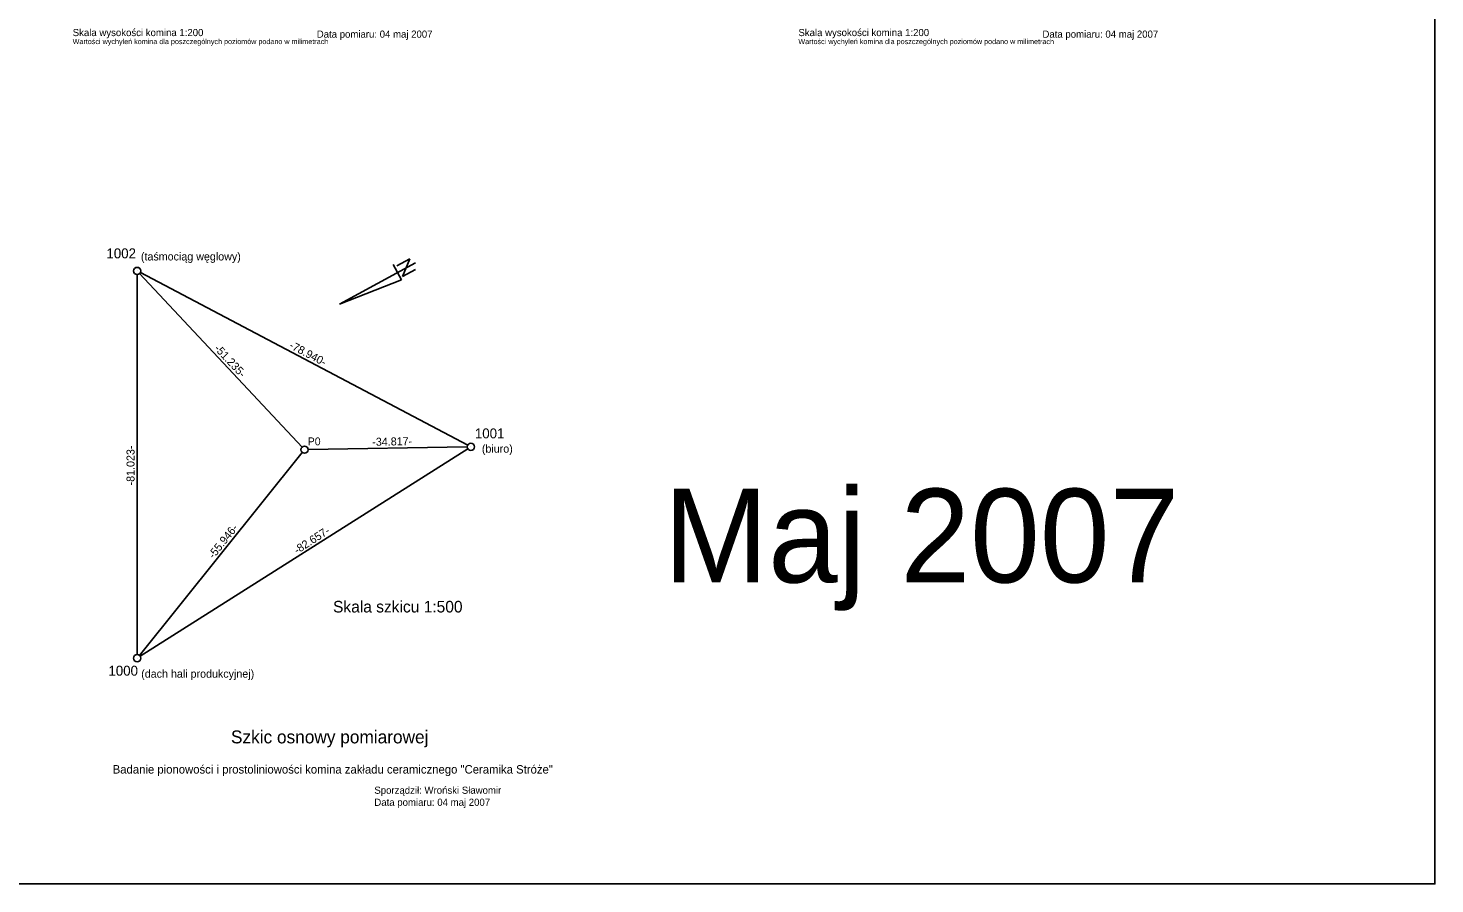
# Model space of a CAD drawing. Extents: x 138 to 264, y -75 to 121.
# Drawn here: x 196.8 to 257.1, y 47.8 to 84.5 of the extents above; entities that cross this region are included whole.
import ezdxf

# ---------------------------------------------------------------- set-up
doc = ezdxf.new("R2010")
doc.units = 0
for name, color, linetype in [('15 listopad 2008', 7, 'Continuous'), ('Default', 7, 'Continuous'), ('Opisy', 7, 'Continuous'), ('Standard', 7, 'Continuous')]:
    doc.layers.add(name, color=color, linetype=linetype)

msp = doc.modelspace()

# ---------------------------------------------------------------- linework, layer by layer
at = {"layer": '15 listopad 2008'}
msp.add_lwpolyline([(139.203, 110.337), (257.14, 110.337), (257.14, 47.785), (139.203, 47.785)], close=True, dxfattribs=at)
at = {"layer": 'Standard'}
for p, q in [((213.429, 74.415), (210.173, 72.634)), ((212.829, 73.679), (212.481, 74.337)), ((213.19, 74.583), (212.633, 74.286)), ((212.88, 73.823), (213.19, 74.583)), ((201.503, 74.063), (201.503, 74.063)), ((201.503, 73.909), (201.503, 69.047)), ((201.608, 73.951), (208.573, 66.513)), ((201.639, 73.991), (215.675, 66.593)), ((210.173, 72.634), (212.829, 73.679)), ((213.437, 74.12), (212.88, 73.823)), ((201.503, 69.047), (201.503, 67.567)), ((201.503, 67.567), (201.503, 57.616)), ((215.681, 66.439), (201.632, 57.544)), ((208.832, 66.403), (215.657, 66.519)), ((215.811, 66.522), (215.811, 66.522)), ((208.582, 66.281), (201.599, 57.582)), ((201.503, 57.462), (201.503, 57.462))]:
    msp.add_line(p, q, dxfattribs=at)
for centre in [(201.503, 74.063), (208.679, 66.401), (215.811, 66.522), (201.503, 57.462)]:
    msp.add_circle(centre, 0.154, dxfattribs=at)

# ---------------------------------------------------------------- texts
at = {"layer": 'Default'}
msp.add_text('Maj 2007', height=4.0171, dxfattribs=at).set_placement((224.08, 60.708))
at = {"layer": 'Opisy'}
for s, height, p in [('Skala wysokości komina 1:200', 0.30766, (198.739, 84.132)), ('Skala wysokości komina 1:200', 0.30766, (229.853, 84.132)), ('Wartości wychyleń komina dla poszczególnych poziomów podano w milimetrach', 0.22315, (198.736, 83.789)), ('Data pomiaru: 04 maj 2007', 0.30766, (209.202, 84.064)), ('Wartości wychyleń komina dla poszczególnych poziomów podano w milimetrach', 0.22315, (229.85, 83.789)), ('Data pomiaru: 04 maj 2007', 0.30766, (240.316, 84.064))]:
    msp.add_text(s, height=height, dxfattribs=at).set_placement(p)
at = {"layer": 'Standard'}
for s, height, p in [('1002', 0.426, (200.184, 74.604)), ('(taśmociąg węglowy)', 0.34308, (201.663, 74.513)), ('1001', 0.426, (215.981, 66.886)), ('P0', 0.3382, (208.814, 66.588)), ('(biuro)', 0.3431, (216.281, 66.273)), ('Skala szkicu 1:500', 0.49797, (209.9, 59.421)), ('1000', 0.426, (200.27, 56.711)), ('(dach hali produkcyjnej)', 0.34308, (201.675, 56.624)), ('Szkic osnowy pomiarowej', 0.55314, (205.523, 53.809)), ('Badanie pionowości i prostoliniowości komina zakładu ceramicznego "Ceramika Stróże"', 0.36281, (200.453, 52.514)), ('Sporządził: Wroński Sławomir', 0.30766, (211.671, 51.647)), ('Data pomiaru: 04 maj 2007', 0.30766, (211.671, 51.13))]:
    msp.add_text(s, height=height, dxfattribs=at).set_placement(p)
for s, rotation, p in [('-51.235-', 313.18745, (204.781, 70.716)), ('-78.940-', 332.12805, (207.99, 70.772)), ('-81.023-', 90, (201.389, 64.869)), ('-34.817-', 1.09229, (211.586, 66.565)), ('-55.946-', 51.39237, (204.78, 61.702)), ('-82.657-', 32.82854, (208.359, 61.913))]:
    msp.add_text(s, height=0.3431, rotation=rotation, dxfattribs=at).set_placement(p)

doc.saveas('drawing.dxf')
